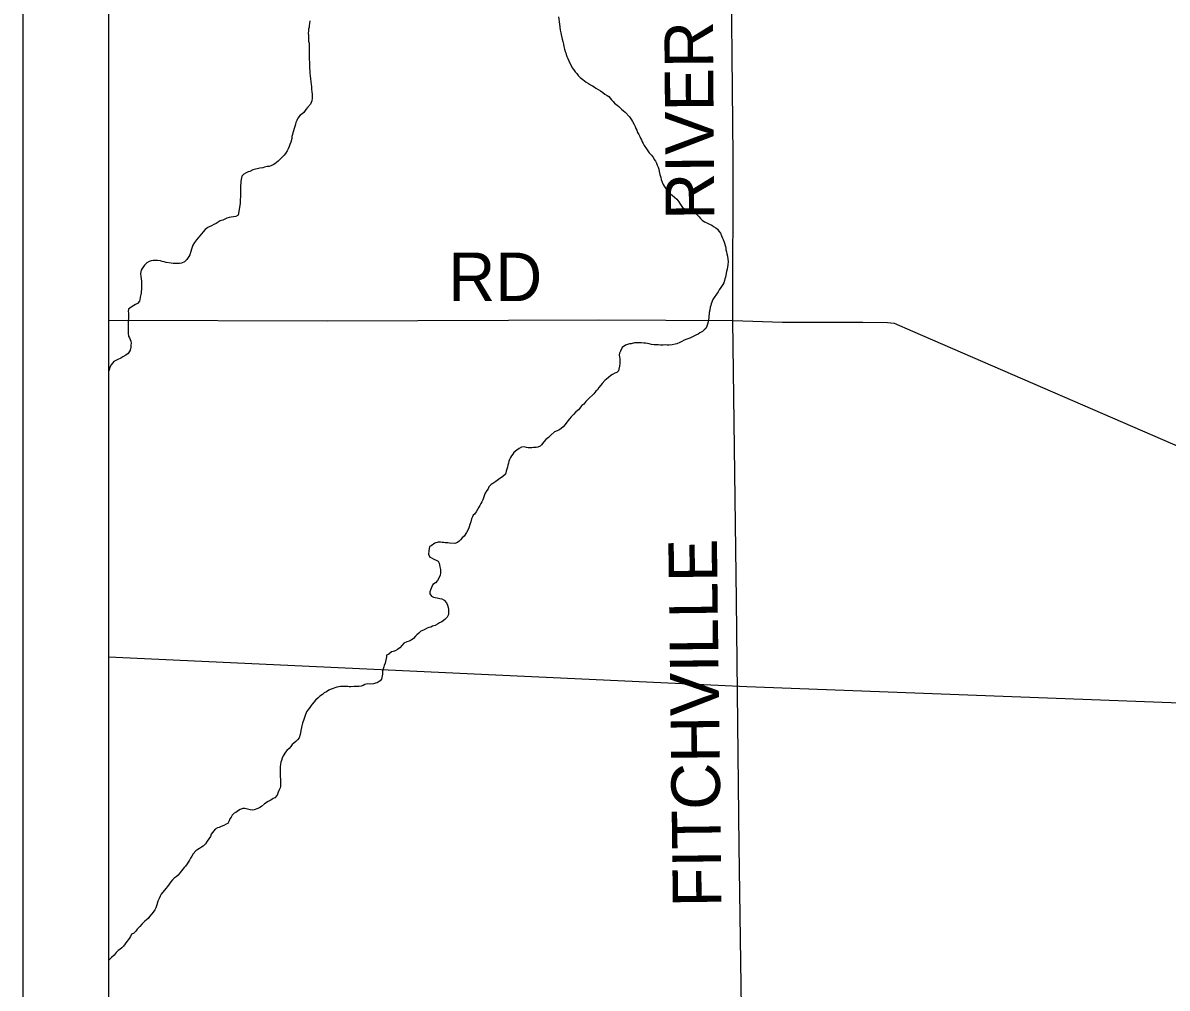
# Model space of a CAD drawing. Extents: x 0 to 34, y 0 to 22.
# Drawn here: x 2 to 3.337, y 18.093 to 19.221 of the extents above; entities that cross this region are included whole.
import ezdxf

# ---------------------------------------------------------------- set-up
doc = ezdxf.new("R2010")
doc.units = 0
for name, color, linetype in [('GM_X_Corporation', 7, 'Continuous'), ('GM_X_Minor_River', 7, 'Continuous'), ('GM_X_Rail_Line', 7, 'Continuous'), ('GM_X_Township_Road', 7, 'Continuous'), ('GM_X_Township_Road_Text', 7, 'Continuous'), ('SH_Data', 7, 'Continuous')]:
    doc.layers.add(name, color=color, linetype=linetype)

msp = doc.modelspace()

# ---------------------------------------------------------------- linework, layer by layer
at = {"layer": 'GM_X_Corporation'}
for points in [[(2.1, 20.3879), (2.1, 14.1)], [(2.1, 20.3879), (2.1, 15.3574)]]:
    msp.add_lwpolyline(points, dxfattribs=at)
at = {"layer": 'GM_X_Minor_River'}
for points in [[(2.3352, 19.2236), (2.3348, 19.2206), (2.3344, 19.2183), (2.3344, 19.2164), (2.334, 19.2141), (2.334, 19.2118), (2.3336, 19.2092), (2.334, 19.2065), (2.334, 19.2031), (2.334, 19.2), (2.3344, 19.1974), (2.3344, 19.1947), (2.3344, 19.1909), (2.3344, 19.1875), (2.3344, 19.1848), (2.3344, 19.1803), (2.3347, 19.1784), (2.3351, 19.1753), (2.3351, 19.173), (2.3351, 19.1704), (2.3355, 19.1631), (2.3359, 19.159), (2.3362, 19.1563), (2.3366, 19.1525), (2.337, 19.1494), (2.3374, 19.1468), (2.3374, 19.1437), (2.3377, 19.1407), (2.3381, 19.138), (2.3381, 19.1354), (2.3381, 19.1335), (2.3377, 19.1301), (2.3362, 19.1262), (2.3328, 19.1225), (2.3305, 19.1202), (2.3282, 19.1167), (2.3259, 19.1148), (2.324, 19.1133), (2.3214, 19.1099), (2.3202, 19.1072), (2.3191, 19.105), (2.3183, 19.1015), (2.3172, 19.0977), (2.3164, 19.0951), (2.3156, 19.0928), (2.3153, 19.0909), (2.3145, 19.0886), (2.3145, 19.0863), (2.313, 19.0818), (2.3118, 19.0791), (2.3111, 19.0768), (2.3099, 19.0742), (2.3088, 19.0719), (2.3069, 19.0688), (2.3054, 19.0666)], [(2.6259, 19.2283), (2.627, 19.2199), (2.6277, 19.2161), (2.6281, 19.2127), (2.6289, 19.2097), (2.6296, 19.2059), (2.6304, 19.2024), (2.6311, 19.1994), (2.6319, 19.1964), (2.6323, 19.1937), (2.633, 19.1907), (2.6338, 19.188), (2.6346, 19.1861), (2.6349, 19.1842), (2.6357, 19.1819), (2.6368, 19.1796)], [(2.6368, 19.1796), (2.638, 19.177), (2.6391, 19.1743), (2.6406, 19.1716), (2.6421, 19.1686), (2.644, 19.1663), (2.6456, 19.164), (2.6474, 19.1621), (2.649, 19.1598), (2.6512, 19.1576), (2.6543, 19.1553), (2.6562, 19.1537), (2.6585, 19.1522), (2.6611, 19.1503), (2.6634, 19.1488), (2.6657, 19.1477), (2.6676, 19.1465), (2.6698, 19.145), (2.6725, 19.1435), (2.6752, 19.1419), (2.6778, 19.14), (2.6801, 19.1381), (2.6828, 19.1366), (2.6847, 19.1351), (2.6862, 19.1332), (2.6881, 19.1313), (2.69, 19.1294), (2.6915, 19.1275), (2.6945, 19.1252), (2.6964, 19.1237), (2.6998, 19.1206), (2.7021, 19.1187), (2.704, 19.1168), (2.7089, 19.1115), (2.7112, 19.1081), (2.7124, 19.1062), (2.7143, 19.1027), (2.7154, 19.1001), (2.7165, 19.0978), (2.7177, 19.0959), (2.7184, 19.0932), (2.7199, 19.0909), (2.7211, 19.0887), (2.7218, 19.0864), (2.723, 19.0845), (2.7237, 19.0822), (2.7249, 19.0803), (2.726, 19.078), (2.7287, 19.0742), (2.7302, 19.0719), (2.7321, 19.0696), (2.7347, 19.0666), (2.737, 19.0635), (2.7378, 19.0616), (2.7393, 19.0597), (2.7404, 19.0575), (2.7412, 19.0552), (2.7423, 19.0525), (2.7431, 19.0502), (2.7438, 19.0476), (2.7446, 19.0441), (2.7454, 19.0407), (2.7461, 19.0381), (2.7472, 19.035), (2.7484, 19.0323), (2.7495, 19.0304), (2.751, 19.0282), (2.7526, 19.0263), (2.7545, 19.0236), (2.7571, 19.0213), (2.759, 19.0198), (2.7617, 19.0175), (2.7643, 19.0152), (2.7666, 19.0122), (2.7677, 19.0103), (2.7708, 19.0057), (2.775, 19.003), (2.7768, 19.0023), (2.7795, 19.0015), (2.7818, 19.0008), (2.7844, 18.9992), (2.7867, 18.9981), (2.7886, 18.9966), (2.7905, 18.9947), (2.792, 18.9928), (2.7939, 18.9909), (2.7966, 18.9889), (2.8, 18.9874), (2.8023, 18.9859), (2.8053, 18.9848), (2.8072, 18.9832), (2.8099, 18.9817), (2.8118, 18.9802), (2.8133, 18.9779), (2.8152, 18.9756), (2.8163, 18.9726), (2.8175, 18.9699), (2.8186, 18.968), (2.8197, 18.965), (2.8213, 18.96), (2.8216, 18.9581)], [(2.3054, 19.0666), (2.3027, 19.0639), (2.2985, 19.0597), (2.2966, 19.0582), (2.2943, 19.0567), (2.2924, 19.0555), (2.2898, 19.0544), (2.2879, 19.0536), (2.2856, 19.0533), (2.2822, 19.0525), (2.2803, 19.0518), (2.2768, 19.0514), (2.2738, 19.0506), (2.2719, 19.0502), (2.2689, 19.0495), (2.2651, 19.0476), (2.2632, 19.0472), (2.2609, 19.0461), (2.2582, 19.0445), (2.2559, 19.0423), (2.2556, 19.0404), (2.2548, 19.0362), (2.2544, 19.029), (2.2544, 19.0232), (2.2544, 19.0179), (2.254, 19.0149), (2.254, 19.0107), (2.2536, 19.0077), (2.2529, 19.0035), (2.2525, 19.0008), (2.2517, 18.9966), (2.2487, 18.9951), (2.246, 18.9947), (2.2433, 18.9944), (2.2411, 18.994), (2.2384, 18.9932), (2.2361, 18.9921), (2.2338, 18.9909), (2.2304, 18.9898), (2.2281, 18.9883), (2.2259, 18.9868), (2.2232, 18.9856), (2.2205, 18.9841), (2.2179, 18.983), (2.216, 18.9822), (2.2129, 18.9799), (2.2106, 18.9773), (2.2087, 18.9746), (2.2068, 18.9723), (2.2049, 18.97), (2.203, 18.9678), (2.2004, 18.9647), (2.1985, 18.9617), (2.1977, 18.959), (2.1969, 18.9567), (2.1962, 18.9541), (2.195, 18.9503), (2.1939, 18.9484), (2.1916, 18.9446), (2.189, 18.9419), (2.1855, 18.9404), (2.1832, 18.94), (2.181, 18.94), (2.1787, 18.94), (2.1757, 18.94), (2.1734, 18.9404), (2.1673, 18.9412), (2.165, 18.9419), (2.1627, 18.9423), (2.1608, 18.9431), (2.1574, 18.9438), (2.154, 18.9438), (2.1521, 18.9438), (2.1498, 18.9431), (2.1475, 18.9423), (2.1449, 18.9408), (2.1422, 18.9382), (2.1395, 18.9344), (2.1384, 18.9325), (2.1376, 18.9286), (2.138, 18.9245), (2.1384, 18.9226), (2.1388, 18.9191), (2.1388, 18.9169), (2.1388, 18.9146), (2.1388, 18.9119), (2.1388, 18.9096), (2.1384, 18.9077), (2.1384, 18.9058), (2.138, 18.9039), (2.1372, 18.9009), (2.1365, 18.8978), (2.1361, 18.8959), (2.1338, 18.8933), (2.1315, 18.8921), (2.1296, 18.891), (2.1266, 18.8891), (2.1235, 18.8868), (2.1232, 18.8842), (2.1235, 18.8823), (2.1235, 18.8804)], [(2.8216, 18.9581), (2.8216, 18.9562), (2.8224, 18.9536), (2.8228, 18.9513), (2.8235, 18.9486), (2.8239, 18.9452), (2.8243, 18.9425), (2.8239, 18.9387), (2.8231, 18.9334), (2.8224, 18.9307), (2.822, 18.9288), (2.8216, 18.9262), (2.8212, 18.9243), (2.8205, 18.922), (2.8201, 18.9201), (2.8193, 18.9174), (2.8182, 18.9155), (2.8159, 18.9121), (2.8136, 18.9094), (2.8125, 18.9068), (2.8106, 18.9041), (2.8079, 18.9003), (2.8064, 18.898), (2.8045, 18.8931), (2.8041, 18.8912), (2.8033, 18.8889), (2.8029, 18.8855), (2.8022, 18.8828), (2.8018, 18.8771), (2.8014, 18.8741), (2.801, 18.8718), (2.8003, 18.8691), (2.7995, 18.8669), (2.798, 18.8642), (2.7961, 18.8627), (2.7942, 18.8608), (2.7911, 18.8589), (2.7892, 18.8574), (2.7866, 18.8562), (2.7835, 18.8547), (2.7812, 18.8536), (2.7793, 18.8528), (2.7759, 18.8517), (2.7729, 18.8505), (2.7702, 18.849), (2.7676, 18.8479), (2.7641, 18.8464), (2.7622, 18.846), (2.7588, 18.8452), (2.7554, 18.8448), (2.7531, 18.8448), (2.7505, 18.8452), (2.7482, 18.8448), (2.7451, 18.8448), (2.7425, 18.8452), (2.7398, 18.8452), (2.7379, 18.8452), (2.7345, 18.8456), (2.7318, 18.8464), (2.7299, 18.8468), (2.7277, 18.8471), (2.7258, 18.8471), (2.7227, 18.8475), (2.7201, 18.8475), (2.7174, 18.8475), (2.7147, 18.8475), (2.7109, 18.8464), (2.709, 18.8464), (2.7068, 18.8456), (2.7041, 18.8445), (2.7003, 18.8418), (2.6984, 18.8377), (2.6973, 18.8354), (2.6969, 18.8335), (2.6973, 18.8308), (2.6976, 18.8289), (2.6976, 18.827), (2.6976, 18.8232), (2.6972, 18.8202), (2.6965, 18.8167), (2.6961, 18.8145), (2.6942, 18.8129), (2.6919, 18.8118), (2.6892, 18.8103), (2.6873, 18.8091), (2.6843, 18.8069), (2.682, 18.805), (2.6801, 18.8034), (2.6771, 18.8), (2.6756, 18.7981), (2.6733, 18.7951), (2.6714, 18.7924), (2.6695, 18.7909), (2.6672, 18.7879), (2.6607, 18.7814), (2.6581, 18.7787), (2.6554, 18.7757), (2.6531, 18.7742), (2.6493, 18.7689), (2.6463, 18.7666), (2.6436, 18.7635)], [(2.1235, 18.8804), (2.1235, 18.8773), (2.1235, 18.8754), (2.1231, 18.8735), (2.1231, 18.8712), (2.1231, 18.8689), (2.1231, 18.867), (2.1231, 18.8651), (2.1231, 18.8625), (2.1231, 18.8602), (2.1231, 18.8583), (2.1235, 18.8553), (2.1246, 18.8534), (2.1254, 18.8511), (2.1262, 18.8492), (2.1265, 18.8469), (2.1261, 18.8446), (2.1261, 18.8423), (2.1254, 18.8389), (2.1242, 18.837), (2.1231, 18.8351), (2.1204, 18.8328), (2.117, 18.8309), (2.1144, 18.8294), (2.1109, 18.8279), (2.1087, 18.8267), (2.1064, 18.8256), (2.1033, 18.8218), (2.1018, 18.8188), (2.1007, 18.8153), (2.1, 18.814)], [(2.6436, 18.7635), (2.6409, 18.7609), (2.6387, 18.7586), (2.6356, 18.7548), (2.6337, 18.7521), (2.6314, 18.7491), (2.6291, 18.7472), (2.6265, 18.7453), (2.6246, 18.7445), (2.6212, 18.7434), (2.617, 18.7396), (2.6143, 18.7366), (2.6113, 18.7343), (2.609, 18.7316), (2.6063, 18.7282), (2.6044, 18.7267), (2.6018, 18.7255), (2.5999, 18.7252), (2.5968, 18.7252), (2.5949, 18.7248), (2.593, 18.7248), (2.5904, 18.7248), (2.5885, 18.7252), (2.5858, 18.7259), (2.5828, 18.7256), (2.5801, 18.724), (2.5771, 18.7218), (2.5736, 18.7191), (2.5725, 18.7172), (2.571, 18.7153), (2.5698, 18.7134), (2.5687, 18.7111), (2.5679, 18.7092), (2.5675, 18.7069), (2.5668, 18.7043), (2.5664, 18.702), (2.5656, 18.6997), (2.5649, 18.6974), (2.5641, 18.694), (2.5611, 18.691), (2.5557, 18.6876), (2.5527, 18.6853), (2.5493, 18.683), (2.5474, 18.6819), (2.5447, 18.6792), (2.5436, 18.6769), (2.5424, 18.675), (2.5401, 18.6716), (2.5394, 18.6697), (2.5386, 18.6674), (2.5375, 18.664), (2.5363, 18.6617), (2.5352, 18.6598), (2.5341, 18.6571), (2.5329, 18.6552), (2.5314, 18.6526), (2.5299, 18.6499), (2.528, 18.6473), (2.5261, 18.6461), (2.5253, 18.6442), (2.5245, 18.6419), (2.5234, 18.6381), (2.5222, 18.6351), (2.5215, 18.6324), (2.5207, 18.6302), (2.5184, 18.6256), (2.5158, 18.6214), (2.5135, 18.6195), (2.5116, 18.6172), (2.5097, 18.6157), (2.5078, 18.6142), (2.5047, 18.6127), (2.4987, 18.6134), (2.4968, 18.6138), (2.4937, 18.6138), (2.4918, 18.6142), (2.4899, 18.6142), (2.488, 18.6146), (2.4854, 18.6146), (2.4816, 18.6134), (2.477, 18.61), (2.4751, 18.6093), (2.4743, 18.6043), (2.474, 18.6005), (2.4758, 18.5971), (2.4777, 18.596), (2.4804, 18.5944), (2.4831, 18.5933), (2.4853, 18.5921), (2.4865, 18.5899), (2.4869, 18.588), (2.4872, 18.5857), (2.488, 18.5826), (2.488, 18.5788), (2.4876, 18.5754), (2.4846, 18.5697), (2.4823, 18.567), (2.4792, 18.5648), (2.4777, 18.5614), (2.4766, 18.5594), (2.4758, 18.5564)], [(2.4758, 18.5564), (2.4758, 18.5541), (2.4777, 18.5515), (2.48, 18.5503), (2.4819, 18.5499), (2.4842, 18.5492), (2.4872, 18.5488), (2.4895, 18.5484), (2.4925, 18.5465), (2.4952, 18.5435), (2.4963, 18.5408), (2.4971, 18.5381), (2.4974, 18.5362), (2.4974, 18.5332), (2.4974, 18.5301), (2.4959, 18.5267), (2.4933, 18.5241), (2.4898, 18.5214), (2.4868, 18.5203), (2.4845, 18.5187), (2.4818, 18.5172), (2.4788, 18.5161), (2.4769, 18.515), (2.4746, 18.5146), (2.4723, 18.5138), (2.4682, 18.5115), (2.4651, 18.5104), (2.4628, 18.5081), (2.4606, 18.5062), (2.4587, 18.5047), (2.4564, 18.502), (2.4537, 18.4998), (2.4514, 18.4986), (2.4488, 18.4979), (2.4453, 18.4963), (2.4434, 18.4941), (2.4404, 18.491), (2.4377, 18.4891), (2.4351, 18.4876), (2.4328, 18.4868), (2.4309, 18.4861), (2.4275, 18.4834), (2.4248, 18.4823), (2.4248, 18.4804), (2.4233, 18.4732), (2.4221, 18.4705), (2.4218, 18.4686), (2.4202, 18.4637), (2.4202, 18.4602), (2.4198, 18.4583), (2.4191, 18.4545), (2.4176, 18.4522), (2.4141, 18.45), (2.4122, 18.4496), (2.4096, 18.4488), (2.4058, 18.4485), (2.4031, 18.4488), (2.3997, 18.4481), (2.3978, 18.4469), (2.3955, 18.4462), (2.3925, 18.4458), (2.3898, 18.4458), (2.3872, 18.4458), (2.3834, 18.4454), (2.3815, 18.4454), (2.3796, 18.4458), (2.3773, 18.4458), (2.375, 18.4458), (2.3731, 18.4458), (2.3712, 18.4458), (2.3693, 18.4454), (2.367, 18.4451), (2.3647, 18.4443), (2.3625, 18.4435), (2.3602, 18.4428), (2.3575, 18.4413), (2.3548, 18.4397), (2.3522, 18.4382), (2.3503, 18.4363), (2.3472, 18.4344), (2.345, 18.4325), (2.3419, 18.4299), (2.3404, 18.428), (2.3381, 18.4253), (2.337, 18.4234), (2.3354, 18.4211), (2.3339, 18.4192), (2.3313, 18.4162), (2.3297, 18.4109), (2.3282, 18.4071), (2.3267, 18.4029), (2.3259, 18.3998), (2.3255, 18.3979), (2.3248, 18.3945), (2.3244, 18.3915), (2.324, 18.3896), (2.3229, 18.3858), (2.321, 18.3835), (2.3191, 18.3816), (2.3168, 18.3797), (2.3149, 18.3778)], [(2.3149, 18.3778), (2.313, 18.3755), (2.3111, 18.3732), (2.3084, 18.371), (2.3069, 18.369), (2.3042, 18.3649), (2.3031, 18.3622), (2.3023, 18.3592), (2.3016, 18.3573), (2.3012, 18.355), (2.3008, 18.3519), (2.3008, 18.3497), (2.3008, 18.3478), (2.3008, 18.3451), (2.3008, 18.3424), (2.3008, 18.3398), (2.3012, 18.3379), (2.3012, 18.3348), (2.3012, 18.3318), (2.3012, 18.3291), (2.3008, 18.3272), (2.2996, 18.3249), (2.2985, 18.3223), (2.297, 18.3189), (2.2943, 18.3158), (2.2924, 18.3147), (2.2897, 18.3128), (2.2867, 18.3113), (2.2825, 18.3086), (2.2787, 18.3056), (2.2768, 18.3044), (2.2745, 18.3033), (2.2703, 18.3018), (2.2681, 18.3014), (2.2658, 18.3018), (2.2624, 18.3025), (2.2593, 18.3033), (2.257, 18.3033), (2.254, 18.3022), (2.2521, 18.301), (2.2487, 18.2987), (2.2468, 18.2976), (2.2445, 18.2953), (2.2434, 18.293), (2.2418, 18.2911), (2.2411, 18.2889), (2.2395, 18.2858), (2.2376, 18.2847), (2.235, 18.2832), (2.2319, 18.282), (2.2293, 18.2809), (2.2274, 18.2805), (2.2247, 18.279), (2.2202, 18.2733), (2.2194, 18.2706), (2.2175, 18.2676), (2.2152, 18.2649), (2.2133, 18.2619), (2.2106, 18.2592), (2.2087, 18.2581), (2.2065, 18.2566), (2.2046, 18.2554), (2.2023, 18.2539), (2.1992, 18.2501), (2.1973, 18.2474), (2.1958, 18.2452), (2.1947, 18.2429), (2.1931, 18.2406), (2.192, 18.2387), (2.1901, 18.236), (2.1886, 18.2341), (2.1871, 18.2322), (2.1855, 18.2303), (2.184, 18.2284), (2.1813, 18.2254), (2.1791, 18.2235), (2.1768, 18.2216), (2.1749, 18.2197), (2.173, 18.2174), (2.1711, 18.2148), (2.1692, 18.2121), (2.1669, 18.2098), (2.1654, 18.2079), (2.1631, 18.2049), (2.1616, 18.203), (2.1604, 18.2007), (2.1593, 18.198), (2.1578, 18.195), (2.1566, 18.1908), (2.1555, 18.187), (2.1543, 18.1847), (2.1524, 18.1821), (2.1509, 18.1802), (2.1479, 18.1771), (2.1463, 18.1748), (2.1444, 18.1729), (2.1425, 18.1714), (2.1395, 18.1684), (2.1368, 18.1653), (2.1334, 18.1623), (2.1319, 18.16)], [(2.1319, 18.16), (2.1292, 18.157), (2.1269, 18.1562), (2.1258, 18.1536), (2.1235, 18.1501), (2.1216, 18.1479), (2.1197, 18.1452), (2.1174, 18.1425), (2.1155, 18.1403), (2.1132, 18.1384), (2.1113, 18.1372), (2.109, 18.1349), (2.1068, 18.1319), (2.1037, 18.1292), (2.1, 18.1255)]]:
    msp.add_lwpolyline(points, dxfattribs=at)
at = {"layer": 'GM_X_Rail_Line'}
msp.add_lwpolyline([(2.1, 18.4805), (2.8461, 18.4459), (3.8274, 18.4086), (4.0038, 18.4053), (4.1245, 18.4086), (4.3015, 18.4114), (4.5799, 18.4555), (5.3876, 18.5934), (5.9987, 18.7127), (6.6286, 18.8295), (7.0292, 18.9027)], dxfattribs=at)
at = {"layer": 'GM_X_Township_Road'}
for points in [[(2.8299, 18.8735), (2.8303, 19.065), (2.8273, 19.3405), (2.8254, 19.51), (2.8254, 19.5256), (2.8278, 19.5381), (2.8424, 19.5943), (2.879, 19.7279), (2.889, 19.7716), (2.8964, 19.8073), (2.903, 19.8491), (2.9089, 19.8864)], [(2.1, 18.8739), (2.3562, 18.873), (2.6733, 18.8741), (2.8299, 18.8735), (2.8879, 18.8717), (2.9816, 18.8714), (3.0104, 18.8713), (3.0183, 18.8705), (3.0399, 18.8609), (3.5538, 18.6382), (3.5902, 18.6219), (3.6033, 18.6141), (3.6082, 18.6077)], [(2.8442, 17.8697), (2.8403, 18.0431), (2.8371, 18.2593), (2.8342, 18.5466), (2.8299, 18.8735)]]:
    msp.add_lwpolyline(points, dxfattribs=at)
at = {"layer": 'SH_Data'}
for p, q in [((2, 21), (2, 14)), ((2.1, 20.9), (2.1, 14.1))]:
    msp.add_line(p, q, dxfattribs=at)

# ---------------------------------------------------------------- texts
at = {"layer": 'GM_X_Township_Road_Text'}
for s, rotation, p in [('RIVER', 90.4372, (2.8082, 18.9914)), ('RD', 0, (2.4972, 18.8961)), ('FITCHVILLE', 90.7148, (2.8165, 18.1881))]:
    msp.add_text(s, height=0.05682, rotation=rotation, dxfattribs=at).set_placement(p)

doc.saveas('drawing.dxf')
